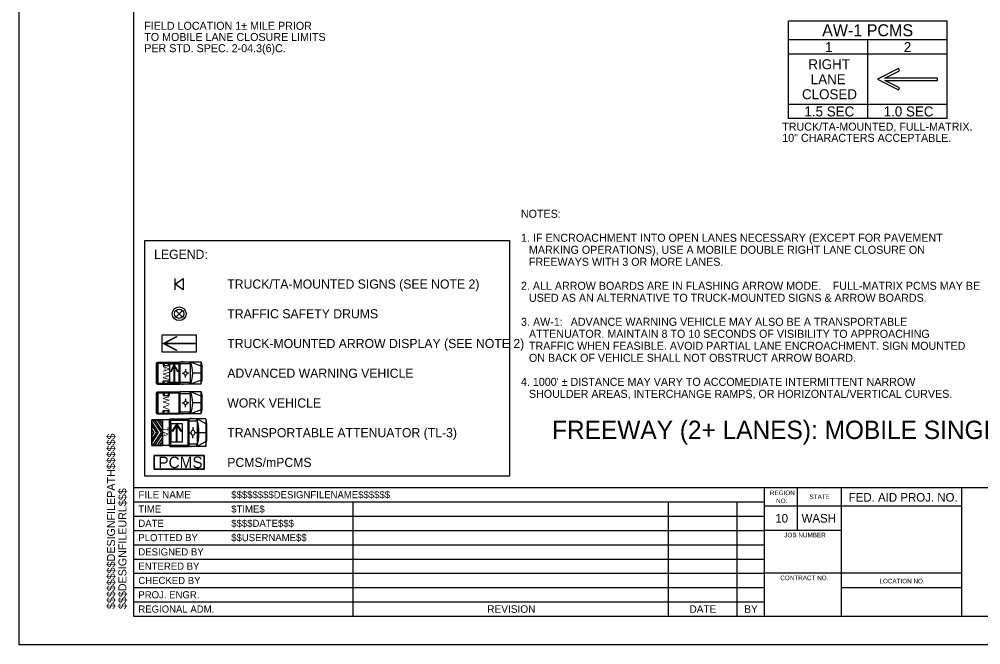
# Model space of a CAD drawing. Extents: x 0 to 17, y 0 to 11.
# Drawn here: x 0 to 8.41, y 0 to 5.47 of the extents above; entities that cross this region are included whole.
import ezdxf

# ---------------------------------------------------------------- set-up
doc = ezdxf.new("R2010")
doc.units = 0
for name, color, linetype in [('SH_GI_PlotLimits', 7, 'Continuous'), ('SH_GI_SheetBorder1', 7, 'Continuous'), ('SH_GI_SheetBorder2', 7, 'Continuous'), ('SH_GI_SheetBorder3', 7, 'Continuous'), ('SH_GI_SheetTextInCells', 7, 'Continuous'), ('SH_GI_TitleBlockText', 7, 'Continuous'), ('TR_SN_SignNotes', 7, 'Continuous'), ('TR_WZ_PCMS', 7, 'Continuous'), ('TR_WZ_PortableChangeMessageSign', 7, 'Continuous'), ('TR_WZ_PortableSignMountBlk-Org', 7, 'Continuous'), ('TR_WZ_ProtectiveVehicle', 7, 'Continuous'), ('TR_WZ_TrafficSafetyDrum', 7, 'Continuous'), ('TR_WZ_TransportableAttenuator', 7, 'Continuous'), ('TR_WZ_WorkZoneTextCurrent', 7, 'Continuous')]:
    doc.layers.add(name, color=color, linetype=linetype)

msp = doc.modelspace()

# ---------------------------------------------------------------- linework, layer by layer
at = {"layer": 'SH_GI_PlotLimits'}
msp.add_lwpolyline([(0, 11), (17, 11), (17, 0), (0, 0)], close=True, dxfattribs=at)
at = {"layer": 'SH_GI_SheetBorder1'}
for p, q in [((8.245, 1.2125), (6.52, 1.2125)), ((1, 1.125), (2.92, 1.125)), ((2.92, 1.125), (6.52, 1.125)), ((1, 1), (2.92, 1)), ((2.92, 1), (6.52, 1)), ((1, 0.875), (2.92, 0.875)), ((2.92, 0.875), (6.52, 0.875)), ((1, 0.75), (2.92, 0.75)), ((2.92, 0.75), (6.52, 0.75)), ((1, 0.625), (2.92, 0.625)), ((2.92, 0.625), (6.52, 0.625)), ((1, 0.5), (2.92, 0.5)), ((2.92, 0.5), (6.52, 0.5)), ((7.1913, 0.5), (8.245, 0.5)), ((1, 0.375), (2.92, 0.375))]:
    msp.add_line(p, q, dxfattribs=at)
at = {"layer": 'SH_GI_SheetBorder2'}
for p, q in [((6.8073, 1), (6.8073, 1.375)), ((7.1913, 1), (6.52, 1)), ((8.245, 0.625), (6.52, 0.625)), ((2.92, 0.375), (6.52, 0.375))]:
    msp.add_line(p, q, dxfattribs=at)
at = {"layer": 'SH_GI_SheetBorder3'}
for p, q in [((1, 10.75), (1, 0.25)), ((1, 1.375), (16.75, 1.375)), ((6.52, 0.25), (6.52, 1.375)), ((7.1913, 0.25), (7.1913, 1.375)), ((8.245, 0.25), (8.245, 1.375)), ((1, 1.25), (6.52, 1.25)), ((2.92, 0.25), (2.92, 1.25)), ((5.68, 0.25), (5.68, 1.25)), ((6.28, 0.25), (6.28, 1.25)), ((1, 0.25), (16.75, 0.25))]:
    msp.add_line(p, q, dxfattribs=at)
at = {"layer": 'TR_SN_SignNotes'}
msp.add_ellipse((1.5199, 1.8549), major_axis=(0, 0.0231), ratio=0.642144, dxfattribs=at)
at = {"layer": 'TR_WZ_PCMS'}
for points in [[(1.6191, 1.655), (1.6191, 1.535), (1.1791, 1.535), (1.1791, 1.655), (1.6191, 1.655)], [(1.1791, 1.655), (1.1791, 1.535), (1.6191, 1.535), (1.6191, 1.655), (1.1791, 1.655)]]:
    msp.add_lwpolyline(points, dxfattribs=at)
at = {"layer": 'TR_WZ_PortableChangeMessageSign'}
for p, q in [((6.7302, 5.4586), (8.1162, 5.4586)), ((6.7302, 4.6018), (6.7302, 5.4586)), ((8.1162, 4.6018), (8.1162, 5.4586)), ((8.1162, 5.2906), (6.7302, 5.2906)), ((7.4232, 4.6018), (7.4232, 5.2906)), ((7.4232, 5.1646), (6.7302, 5.1646)), ((8.1162, 5.1646), (7.4232, 5.1646)), ((7.6912, 5.0395), (7.5072, 4.9462)), ((8.0322, 4.9567), (7.5724, 4.9567)), ((7.5724, 4.9357), (8.0322, 4.9357)), ((8.0322, 4.9357), (8.0322, 4.9567)), ((6.7302, 4.7278), (7.4232, 4.7278)), ((7.4232, 4.7278), (8.1162, 4.7278)), ((8.1162, 4.6018), (6.7302, 4.6018))]:
    msp.add_line(p, q, dxfattribs=at)
for points in [[(7.5724, 4.9567), (7.7006, 5.0208), (7.6959, 5.0302), (7.6912, 5.0395)], [(7.5072, 4.9462), (7.6912, 4.8528), (7.6959, 4.8622), (7.7006, 4.8715), (7.5724, 4.9357)]]:
    msp.add_lwpolyline(points, dxfattribs=at)
at = {"layer": 'TR_WZ_PortableSignMountBlk-Org'}
msp.add_line((1.3631, 3.105), (1.3631, 3.205), dxfattribs=at)
msp.add_lwpolyline([(1.3631, 3.155), (1.435, 3.205), (1.435, 3.105)], close=True, dxfattribs=at)
at = {"layer": 'TR_WZ_ProtectiveVehicle'}
for p, q in [((1.1993, 2.288), (1.1993, 2.462)), ((1.2035, 2.4678), (1.2078, 2.4678)), ((1.2078, 2.2822), (1.2078, 2.4678)), ((1.2085, 2.471), (1.406, 2.471)), ((1.2085, 2.279), (1.2085, 2.471)), ((1.2141, 2.2867), (1.2141, 2.4633)), ((1.2141, 2.4633), (1.4004, 2.4633)), ((1.2586, 2.4633), (1.2586, 2.4413)), ((1.2586, 2.4413), (1.3114, 2.4413)), ((1.2692, 2.4633), (1.2692, 2.4413)), ((1.3018, 2.4633), (1.3018, 2.4413)), ((1.3114, 2.4633), (1.3114, 2.4413)), ((1.4004, 2.2867), (1.4004, 2.4633)), ((1.406, 2.279), (1.406, 2.471)), ((1.4086, 2.279), (1.4086, 2.471)), ((1.59, 2.471), (1.4086, 2.471)), ((1.4976, 2.4561), (1.4086, 2.4561)), ((1.4334, 2.4737), (1.4225, 2.4737)), ((1.4881, 2.4561), (1.4976, 2.471)), ((1.4976, 2.279), (1.4976, 2.471)), ((1.4993, 2.279), (1.4993, 2.471)), ((1.59, 2.4358), (1.4993, 2.471)), ((1.59, 2.279), (1.59, 2.471)), ((1.59, 2.471), (1.5989, 2.4322)), ((1.1993, 2.3885), (1.2078, 2.3849)), ((1.1993, 2.3615), (1.2078, 2.3651)), ((1.2016, 2.375), (1.2055, 2.375)), ((1.2035, 2.3723), (1.2035, 2.3777)), ((1.4245, 2.3757), (1.4388, 2.3754)), ((1.4406, 2.3753), (1.4406, 2.3753)), ((1.4535, 2.4119), (1.4537, 2.3975)), ((1.4831, 2.3749), (1.471, 2.3749)), ((1.59, 2.375), (1.5171, 2.375)), ((1.5989, 2.3178), (1.5989, 2.4322)), ((1.2035, 2.2822), (1.2078, 2.2822)), ((1.2085, 2.279), (1.406, 2.279)), ((1.2141, 2.2867), (1.4004, 2.2867)), ((1.2586, 2.3087), (1.3114, 2.3087)), ((1.2586, 2.2867), (1.2586, 2.3087)), ((1.2692, 2.2867), (1.2692, 2.3087)), ((1.3018, 2.2867), (1.3018, 2.3087)), ((1.3114, 2.2867), (1.3114, 2.3087)), ((1.4976, 2.2939), (1.4086, 2.2939)), ((1.59, 2.279), (1.4086, 2.279)), ((1.4334, 2.2763), (1.4225, 2.2763)), ((1.4541, 2.3369), (1.4541, 2.3525)), ((1.4976, 2.279), (1.4861, 2.2939)), ((1.59, 2.3142), (1.4993, 2.279)), ((1.59, 2.279), (1.5989, 2.3178)), ((1.1993, 2.028), (1.1993, 2.202)), ((1.2035, 2.2078), (1.2078, 2.2078)), ((1.2078, 2.0222), (1.2078, 2.2078)), ((1.2085, 2.211), (1.406, 2.211)), ((1.2085, 2.019), (1.2085, 2.211)), ((1.2141, 2.0267), (1.2141, 2.2033)), ((1.2141, 2.2033), (1.4004, 2.2033)), ((1.2586, 2.2033), (1.2586, 2.1813)), ((1.2692, 2.2033), (1.2692, 2.1813)), ((1.3018, 2.2033), (1.3018, 2.1813)), ((1.3114, 2.2033), (1.3114, 2.1813)), ((1.4004, 2.0267), (1.4004, 2.2033)), ((1.406, 2.019), (1.406, 2.211)), ((1.4086, 2.019), (1.4086, 2.211)), ((1.59, 2.211), (1.4086, 2.211)), ((1.4976, 2.1961), (1.4086, 2.1961)), ((1.4334, 2.2137), (1.4225, 2.2137)), ((1.4881, 2.1961), (1.4976, 2.211)), ((1.4976, 2.019), (1.4976, 2.211)), ((1.4993, 2.019), (1.4993, 2.211)), ((1.59, 2.1758), (1.4993, 2.211)), ((1.59, 2.019), (1.59, 2.211)), ((1.59, 2.211), (1.5989, 2.1722)), ((1.1993, 2.1285), (1.2078, 2.1249)), ((1.1993, 2.1015), (1.2078, 2.1051)), ((1.2016, 2.115), (1.2055, 2.115)), ((1.2035, 2.1123), (1.2035, 2.1177)), ((1.2586, 2.1813), (1.3114, 2.1813)), ((1.4245, 2.1157), (1.4388, 2.1154)), ((1.4406, 2.1153), (1.4406, 2.1153)), ((1.4535, 2.1519), (1.4537, 2.1375)), ((1.4831, 2.1149), (1.471, 2.1149)), ((1.59, 2.115), (1.5171, 2.115)), ((1.5989, 2.0578), (1.5989, 2.1722)), ((1.2035, 2.0222), (1.2078, 2.0222)), ((1.2085, 2.019), (1.406, 2.019)), ((1.2141, 2.0267), (1.4004, 2.0267)), ((1.2586, 2.0487), (1.3114, 2.0487)), ((1.2586, 2.0267), (1.2586, 2.0487)), ((1.2692, 2.0267), (1.2692, 2.0487)), ((1.3018, 2.0267), (1.3018, 2.0487)), ((1.3114, 2.0267), (1.3114, 2.0487)), ((1.4976, 2.0339), (1.4086, 2.0339)), ((1.59, 2.019), (1.4086, 2.019)), ((1.4541, 2.0769), (1.4541, 2.0925)), ((1.4976, 2.019), (1.4861, 2.0339)), ((1.59, 2.0542), (1.4993, 2.019)), ((1.59, 2.019), (1.5989, 2.0578)), ((1.4334, 2.0163), (1.4225, 2.0163))]:
    msp.add_line(p, q, dxfattribs=at)
for centre, major_axis, start_param, end_param in [((1.2035, 2.462), (0, 0.00586), 0, 1.570796), ((1.3697, 2.375), (0, 0.2015), 4.215667, 5.208926), ((1.2035, 2.288), (0, -0.00586), 4.712389, 6.283185), ((1.2035, 2.202), (0, 0.00586), 0, 1.570796), ((1.3697, 2.115), (0, 0.2015), 4.215667, 5.208926), ((1.2035, 2.028), (0, -0.00586), 4.712389, 6.283185)]:
    msp.add_ellipse(centre, major_axis=major_axis, ratio=0.73155, start_param=start_param, end_param=end_param, dxfattribs=at)
for centre, major_axis in [((1.2035, 2.375), (0, -0.0027)), ((1.4541, 2.375), (0, -0.0185)), ((1.2035, 2.115), (0, -0.0027)), ((1.4541, 2.115), (0, -0.0185))]:
    msp.add_ellipse(centre, major_axis=major_axis, ratio=0.73155, dxfattribs=at)
at = {"layer": 'TR_WZ_TrafficSafetyDrum'}
for p, q in [((1.3708, 2.9233), (1.4273, 2.8667)), ((1.4273, 2.9233), (1.3708, 2.8667))]:
    msp.add_line(p, q, dxfattribs=at)
for radius in [0.06, 0.06, 0.04]:
    msp.add_circle((1.3991, 2.895), radius, dxfattribs=at)
at = {"layer": 'TR_WZ_TransportableAttenuator'}
for p, q in [((1.1591, 1.9172), (1.1591, 1.9464)), ((1.2192, 1.8559), (1.1591, 1.9464)), ((1.1591, 1.9464), (1.1591, 1.9172)), ((1.1653, 1.9678), (1.1857, 1.9678)), ((1.1653, 1.9678), (1.2401, 1.8552)), ((1.1857, 1.9678), (1.1653, 1.9678)), ((1.2534, 1.8651), (1.1857, 1.9678)), ((1.2079, 1.9678), (1.2282, 1.9678)), ((1.2282, 1.9678), (1.2079, 1.9678)), ((1.2079, 1.9678), (1.2534, 1.8983)), ((1.2534, 1.9297), (1.2282, 1.9678)), ((1.3178, 1.9678), (1.2534, 1.9678)), ((1.2534, 1.7426), (1.2534, 1.9678)), ((1.3102, 1.9637), (1.3102, 1.7462)), ((1.3137, 1.971), (1.3173, 1.971)), ((1.3173, 1.971), (1.3173, 1.7389)), ((1.3178, 1.9749), (1.4803, 1.9749)), ((1.3178, 1.9749), (1.3178, 1.735)), ((1.3178, 1.9674), (1.3178, 1.7426)), ((1.3224, 1.9654), (1.3224, 1.7446)), ((1.3224, 1.9654), (1.4757, 1.9654)), ((1.4757, 1.9654), (1.4757, 1.7446)), ((1.4803, 1.9749), (1.4803, 1.735)), ((1.4825, 1.9749), (1.4825, 1.735)), ((1.6317, 1.9749), (1.4825, 1.9749)), ((1.5557, 1.9563), (1.4825, 1.9563)), ((1.5038, 1.9784), (1.4949, 1.9784)), ((1.5557, 1.9749), (1.5462, 1.9563)), ((1.5557, 1.9749), (1.5557, 1.735)), ((1.5571, 1.9749), (1.5571, 1.735)), ((1.6317, 1.931), (1.5571, 1.9749)), ((1.6317, 1.9749), (1.6317, 1.735)), ((1.6317, 1.9749), (1.639, 1.9265)), ((1.1591, 1.9172), (1.1999, 1.8562)), ((1.1591, 1.8239), (1.1591, 1.8863)), ((1.18, 1.8553), (1.1591, 1.8863)), ((1.1591, 1.8863), (1.1591, 1.8239)), ((1.1999, 1.8562), (1.1591, 1.7947)), ((1.1591, 1.7653), (1.2192, 1.8559)), ((1.1591, 1.8239), (1.18, 1.8553)), ((1.2401, 1.8552), (1.1653, 1.7424)), ((1.2534, 1.9297), (1.2534, 1.8983)), ((1.2534, 1.8983), (1.2534, 1.9297)), ((1.2534, 1.8651), (1.2534, 1.845)), ((1.2534, 1.845), (1.2534, 1.8651)), ((1.3102, 1.8718), (1.3173, 1.8674)), ((1.3121, 1.855), (1.3154, 1.855)), ((1.3137, 1.8583), (1.3137, 1.8516)), ((1.4882, 1.8551), (1.5015, 1.8551)), ((1.5051, 1.8545), (1.5051, 1.8545)), ((1.5199, 1.9025), (1.5199, 1.8831)), ((1.5517, 1.8551), (1.5384, 1.8551)), ((1.6317, 1.855), (1.5717, 1.855)), ((1.639, 1.9265), (1.639, 1.7834)), ((1.1591, 1.7653), (1.1591, 1.7947)), ((1.1591, 1.7947), (1.1591, 1.7653)), ((1.1853, 1.7424), (1.2534, 1.845)), ((1.2534, 1.8119), (1.2073, 1.7424)), ((1.2289, 1.7424), (1.2534, 1.7787)), ((1.2534, 1.8119), (1.2534, 1.7787)), ((1.2534, 1.7787), (1.2534, 1.8119)), ((1.3102, 1.838), (1.3173, 1.8426)), ((1.5199, 1.8074), (1.5199, 1.8268)), ((1.6317, 1.7789), (1.5571, 1.735)), ((1.6317, 1.735), (1.639, 1.7834)), ((1.1853, 1.7424), (1.1653, 1.7424)), ((1.1653, 1.7424), (1.1853, 1.7424)), ((1.2289, 1.7424), (1.2073, 1.7424)), ((1.2073, 1.7424), (1.2289, 1.7424)), ((1.3178, 1.7426), (1.2534, 1.7426)), ((1.3137, 1.7389), (1.3173, 1.7389)), ((1.3178, 1.735), (1.4803, 1.735)), ((1.3224, 1.7446), (1.4757, 1.7446)), ((1.5557, 1.7536), (1.4825, 1.7536)), ((1.6317, 1.735), (1.4825, 1.735)), ((1.5028, 1.7316), (1.4939, 1.7316)), ((1.5479, 1.7536), (1.5557, 1.735))]:
    msp.add_line(p, q, dxfattribs=at)
for points in [[(1.5517, 2.563), (1.5517, 2.707), (1.2464, 2.707), (1.2464, 2.563)], [(1.2587, 2.635), (1.3749, 2.697), (1.3782, 2.693), (1.274, 2.6374)], [(1.2587, 2.635), (1.274, 2.6374), (1.274, 2.6326)], [(1.3749, 2.573), (1.2587, 2.635), (1.274, 2.6326), (1.3782, 2.577)], [(1.5395, 2.6326), (1.274, 2.6326), (1.274, 2.6374), (1.5395, 2.6374)], [(1.3183, 2.4564), (1.3951, 2.4564), (1.3951, 2.2936), (1.3183, 2.2936)], [(1.3236, 2.3879), (1.3567, 2.4499), (1.3554, 2.4417), (1.3257, 2.3861)], [(1.3567, 2.4499), (1.358, 2.4417), (1.3554, 2.4417)], [(1.3554, 2.3001), (1.3554, 2.4417), (1.358, 2.4417), (1.358, 2.3001)], [(1.3567, 2.4499), (1.3897, 2.3879), (1.3876, 2.3861), (1.358, 2.4417)], [(1.2534, 1.7424), (1.1591, 1.7424), (1.1591, 1.9678), (1.2534, 1.9678)], [(1.3304, 1.9364), (1.4264, 1.9364), (1.4264, 1.7735), (1.3304, 1.7735)], [(1.3371, 1.8678), (1.3784, 1.9298), (1.3768, 1.9216), (1.3398, 1.866)], [(1.3784, 1.9298), (1.38, 1.9216), (1.3768, 1.9216)], [(1.3768, 1.7801), (1.3768, 1.9216), (1.38, 1.9216), (1.38, 1.7801)], [(1.3784, 1.9298), (1.4198, 1.8678), (1.4171, 1.866), (1.38, 1.9216)]]:
    msp.add_lwpolyline(points, close=True, dxfattribs=at)
msp.add_lwpolyline([(1.2534, 1.9678), (1.1591, 1.9678), (1.1591, 1.7424), (1.2534, 1.7426)], dxfattribs=at)
for centre, major_axis, start_param, end_param in [((1.3137, 1.9637), (0, 0.00732), 6.283185, 7.853982), ((1.4505, 1.8549), (0, 0.2518), 4.215852, 5.209111), ((1.3137, 1.7462), (0, -0.00732), 4.712389, 6.283185)]:
    msp.add_ellipse(centre, major_axis=major_axis, ratio=0.481608, start_param=start_param, end_param=end_param, dxfattribs=at)
for centre, major_axis, ratio in [((1.3137, 1.8549), (0, -0.00338), 0.481608), ((1.5199, 1.8549), (0, -0.0231), 0.642144)]:
    msp.add_ellipse(centre, major_axis=major_axis, ratio=ratio, dxfattribs=at)
at = {"layer": 'TR_WZ_WorkZoneTextCurrent'}
msp.add_lwpolyline([(1.1, 3.535), (4.2886, 3.535), (4.2886, 1.475), (1.1, 1.475)], close=True, dxfattribs=at)

# ---------------------------------------------------------------- texts
at = {"layer": 'SH_GI_SheetTextInCells'}
for s, height, p in [('REGION', 0.04, (6.5662, 1.3088)), ('FILE NAME', 0.065, (1.042, 1.28)), ('NO.', 0.04, (6.6206, 1.2387)), ('STATE', 0.04, (6.9129, 1.2738)), ('FED. AID PROJ. NO.', 0.075, (7.2558, 1.252)), ('TIME', 0.0625, (1.042, 1.1562)), ('DATE', 0.0625, (1.042, 1.0312)), ('10', 0.075, (6.6136, 1.0688)), ('WASH', 0.075, (6.8434, 1.0688)), ('PLOTTED BY', 0.0625, (1.042, 0.9062)), ('JOB NUMBER', 0.04, (6.6925, 0.94)), ('DESIGNED BY', 0.0625, (1.042, 0.7812)), ('ENTERED BY', 0.0625, (1.042, 0.6562)), ('CHECKED BY', 0.0625, (1.042, 0.5312)), ('CONTRACT NO.', 0.04, (6.6574, 0.565)), ('LOCATION NO.', 0.04, (7.5244, 0.537)), ('PROJ. ENGR.', 0.0625, (1.042, 0.4062)), ('REGIONAL ADM.', 0.0625, (1.042, 0.2812)), ('REVISION', 0.066, (4.0938, 0.2795)), ('DATE', 0.066, (5.8627, 0.2795)), ('BY', 0.066, (6.3424, 0.2795))]:
    msp.add_text(s, height=height, dxfattribs=at).set_placement(p)
at = {"layer": 'SH_GI_TitleBlockText'}
for s, p in [('$$$$$$$$DESIGNFILEPATH$$$$$$', (0.8377, 0.3125)), ('$$$DESIGNFILEURL$$$', (0.9375, 0.3125))]:
    msp.add_text(s, height=0.07, rotation=90, dxfattribs=at).set_placement(p)
for s, p in [('$$$$$$$$DESIGNFILENAME$$$$$$', (1.8545, 1.2812)), ('$TIME$', (1.8545, 1.1562)), ('$$$$DATE$$$', (1.8545, 1.0312)), ('$$USERNAME$$', (1.8545, 0.9062))]:
    msp.add_text(s, height=0.0625, dxfattribs=at).set_placement(p)
at = {"layer": 'TR_WZ_PCMS'}
msp.add_text('PCMS', height=0.1, rotation=360, dxfattribs=at).set_placement((1.2173, 1.545))
at = {"layer": 'TR_WZ_PortableChangeMessageSign'}
for s, height, p in [('FIELD LOCATION 1± MILE PRIOR ', 0.07, (1.0938, 5.3789)), ('AW-1 PCMS', 0.105, (7.0234, 5.3221)), ('TO MOBILE LANE CLOSURE LIMITS ', 0.07, (1.0938, 5.2809)), ('PER STD. SPEC. 2-04.3(6)C.', 0.07, (1.0938, 5.1829)), ('1', 0.0875, (7.0494, 5.1838)), ('2', 0.0875, (7.7373, 5.1838)), ('RIGHT', 0.0875, (6.9028, 5.0337)), ('LANE', 0.0875, (6.9235, 4.9024)), ('CLOSED', 0.0875, (6.847, 4.7712)), ('1.5 SEC', 0.0875, (6.8685, 4.621)), ('1.0 SEC', 0.0875, (7.5615, 4.621)), ('TRUCK/TA-MOUNTED, FULL-MATRIX.', 0.07, (6.6743, 4.4968)), ('10" CHARACTERS ACCEPTABLE.', 0.07, (6.6743, 4.3988))]:
    msp.add_text(s, height=height, rotation=360, dxfattribs=at).set_placement(p)
at = {"layer": 'TR_WZ_ProtectiveVehicle'}
for s, p in [('AW', (1.257, 2.4371)), ('WV', (1.257, 2.1743))]:
    msp.add_text(s, height=0.056, rotation=270, dxfattribs=at).set_placement(p)
at = {"layer": 'TR_WZ_TransportableAttenuator'}
msp.add_text('TA', height=0.048, rotation=270, dxfattribs=at).set_placement((1.2567, 1.9047))
at = {"layer": 'TR_WZ_WorkZoneTextCurrent'}
for s, height, p in [('NOTES:', 0.07, (4.3886, 3.7347)), ('1. ', 0.07, (4.3886, 3.5247)), ('IF ENCROACHMENT INTO OPEN LANES NECESSARY (EXCEPT FOR PAVEMENT ', 0.07, (4.4943, 3.5247)), ('LEGEND:', 0.08, (1.18, 3.375)), ('MARKING OPERATIONS), USE A MOBILE DOUBLE RIGHT LANE CLOSURE ON ', 0.07, (4.4586, 3.4197)), ('FREEWAYS WITH 3 OR MORE LANES.', 0.07, (4.4586, 3.3147)), ('TRUCK/TA-MOUNTED SIGNS (SEE NOTE 2)', 0.08, (1.82, 3.115)), ('2. ALL ARROW BOARDS ARE IN FLASHING ARROW MODE. ', 0.07, (4.3886, 3.1047)), ('FULL-MATRIX PCMS MAY BE ', 0.07, (7.1158, 3.1047)), ('USED AS AN ALTERNATIVE TO TRUCK-MOUNTED SIGNS & ARROW BOARDS.', 0.07, (4.4586, 2.9997)), ('TRAFFIC SAFETY DRUMS', 0.08, (1.82, 2.855)), ('3. ', 0.07, (4.3886, 2.7897)), (' ADVANCE WARNING VEHICLE MAY ALSO BE A TRANSPORTABLE ', 0.07, (4.7978, 2.7897)), ('AW-1:', 0.07, (4.4943, 2.7897)), ('ATTENUATOR. MAINTAIN 8 TO 10 SECONDS OF VISIBILITY TO APPROACHING ', 0.07, (4.4586, 2.6847)), ('TRUCK-MOUNTED ARROW DISPLAY (SEE NOTE 2)', 0.08, (1.82, 2.595)), ('TRAFFIC WHEN FEASIBLE. AVOID PARTIAL LANE ENCROACHMENT. SIGN MOUNTED ', 0.07, (4.4586, 2.5797)), ('ON BACK OF VEHICLE SHALL NOT OBSTRUCT ARROW BOARD.', 0.07, (4.4586, 2.4747)), ('ADVANCED WARNING VEHICLE', 0.08, (1.82, 2.335)), ("4. 1000' ± DISTANCE MAY VARY TO ACCOMEDIATE INTERMITTENT NARROW ", 0.07, (4.3886, 2.2647)), ('SHOULDER AREAS, INTERCHANGE RAMPS, OR HORIZONTAL/VERTICAL CURVES. ', 0.07, (4.4586, 2.1597)), ('WORK VEHICLE', 0.08, (1.82, 2.075)), ('FREEWAY (2+ LANES): MOBILE SINGLE RIGHT LANE CLOSURE, EXCLUDING PAVEMENT MARKING OPERATIONS', 0.16, (4.6606, 1.7997)), ('TRANSPORTABLE ATTENUATOR (TL-3)', 0.08, (1.82, 1.815)), ('PCMS/mPCMS', 0.08, (1.82, 1.555))]:
    msp.add_text(s, height=height, rotation=360, dxfattribs=at).set_placement(p)

doc.saveas('drawing.dxf')
